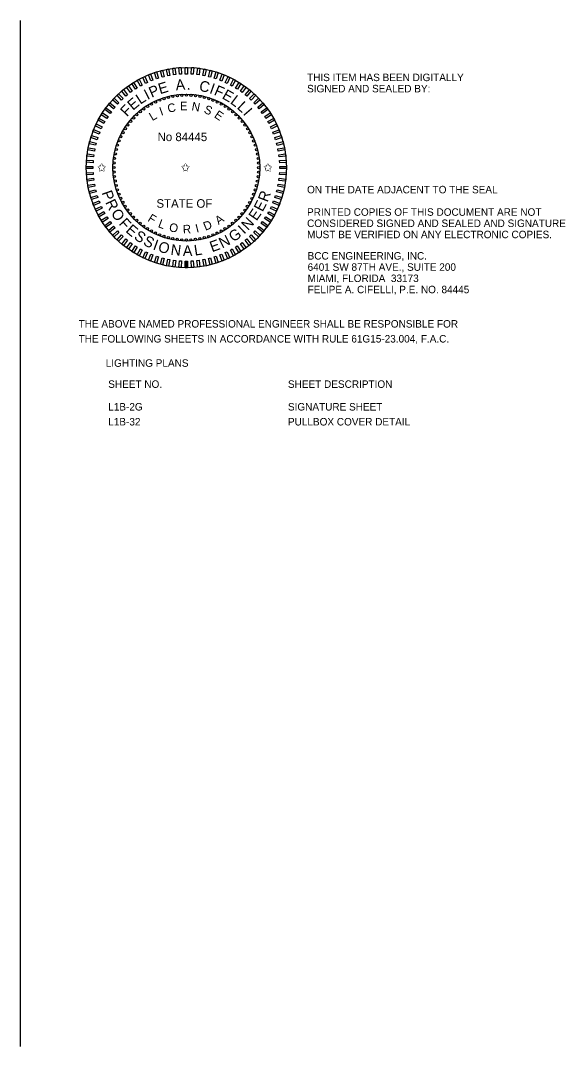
# Model space of a CAD drawing. Extents: x -811.2 to -755.6, y -2295.2 to -2235.1.
# Drawn here: x -760.66 to -755.56, y -2282.15 to -2272.55 of the extents above; entities that cross this region are included whole.
import ezdxf

# ---------------------------------------------------------------- set-up
doc = ezdxf.new("R2010")
doc.units = 0
for name, color, linetype in [('Logo_dp', 7, 'Continuous'), ('NonPlottingEle_dp', 7, 'Continuous'), ('SheetBorder_dp', 7, 'Continuous'), ('TextMisc', 7, 'Continuous'), ('TextNotes', 7, 'Continuous')]:
    doc.layers.add(name, color=color, linetype=linetype)

msp = doc.modelspace()

# ---------------------------------------------------------------- linework, layer by layer
at = {"layer": 'Logo_dp'}
for p, q in [((-759.1177, -2274.859), (-759.1179, -2274.7965)), ((-759.1077, -2274.859), (-759.1079, -2274.7965)), ((-759.0977, -2274.859), (-759.0979, -2274.7965))]:
    msp.add_line(p, q, dxfattribs=at)
for points in [[(-759.2073, -2273.0521), (-759.2273, -2273.0546), (-759.2351, -2272.9927), (-759.2151, -2272.9902)], [(-759.1525, -2273.0476), (-759.1726, -2273.0488), (-759.1765, -2272.9865), (-759.1564, -2272.9852)], [(-759.0975, -2273.0465), (-759.1177, -2273.0465), (-759.1177, -2272.984), (-759.0975, -2272.984)], [(-759.0426, -2273.0488), (-759.0627, -2273.0476), (-759.0588, -2272.9853), (-759.0387, -2272.9865)], [(-758.9879, -2273.0547), (-759.0079, -2273.0521), (-759.0001, -2272.9902), (-758.9801, -2272.9927)], [(-759.471, -2273.1254), (-759.4893, -2273.134), (-759.5159, -2273.0775), (-759.4976, -2273.0689)], [(-759.4203, -2273.1042), (-759.4391, -2273.1116), (-759.4621, -2273.0536), (-759.4433, -2273.0461)], [(-759.3684, -2273.0862), (-759.3876, -2273.0924), (-759.4069, -2273.033), (-759.3877, -2273.0268)], [(-759.3154, -2273.0714), (-759.335, -2273.0765), (-759.3505, -2273.016), (-759.331, -2273.011)], [(-759.2617, -2273.0601), (-759.2815, -2273.0638), (-759.2932, -2273.0025), (-759.2734, -2272.9987)], [(-758.9337, -2273.0639), (-758.9536, -2273.0601), (-758.9419, -2272.9988), (-758.922, -2273.0026)], [(-758.8802, -2273.0765), (-758.8998, -2273.0715), (-758.8842, -2273.011), (-758.8647, -2273.016)], [(-758.8276, -2273.0925), (-758.8468, -2273.0862), (-758.8275, -2273.0268), (-758.8083, -2273.0331)], [(-758.7761, -2273.1117), (-758.7949, -2273.1042), (-758.7719, -2273.0462), (-758.7531, -2273.0536)], [(-758.7259, -2273.1341), (-758.7442, -2273.1255), (-758.7176, -2273.069), (-758.6993, -2273.0776)], [(-759.6138, -2273.2076), (-759.6301, -2273.2195), (-759.6668, -2273.169), (-759.6505, -2273.1571)], [(-759.568, -2273.1772), (-759.585, -2273.1881), (-759.6185, -2273.1353), (-759.6014, -2273.1245)], [(-759.5203, -2273.1498), (-759.538, -2273.1595), (-759.5681, -2273.1048), (-759.5504, -2273.0951)], [(-758.6772, -2273.1596), (-758.6949, -2273.1499), (-758.6648, -2273.0952), (-758.6471, -2273.1049)], [(-758.6302, -2273.1882), (-758.6473, -2273.1773), (-758.6138, -2273.1246), (-758.5968, -2273.1354)], [(-758.5851, -2273.2196), (-758.6015, -2273.2077), (-758.5648, -2273.1572), (-758.5484, -2273.1691)], [(-759.7386, -2273.3151), (-759.7524, -2273.3298), (-759.7979, -2273.2871), (-759.7841, -2273.2723)], [(-759.6993, -2273.2767), (-759.714, -2273.2905), (-759.7567, -2273.245), (-759.742, -2273.2311)], [(-759.6576, -2273.2408), (-759.6732, -2273.2537), (-759.713, -2273.2055), (-759.6974, -2273.1927)], [(-758.5421, -2273.2538), (-758.5576, -2273.2409), (-758.5178, -2273.1928), (-758.5023, -2273.2057)], [(-758.5013, -2273.2906), (-758.516, -2273.2768), (-758.4732, -2273.2313), (-758.4585, -2273.2451)], [(-758.4628, -2273.3299), (-758.4767, -2273.3152), (-758.4312, -2273.2725), (-758.4173, -2273.2872)], [(-759.8096, -2273.3989), (-759.8215, -2273.4153), (-759.872, -2273.3786), (-759.8601, -2273.3622)], [(-759.7754, -2273.3559), (-759.7883, -2273.3714), (-759.8364, -2273.3316), (-759.8235, -2273.3161)], [(-758.427, -2273.3716), (-758.4398, -2273.356), (-758.3917, -2273.3162), (-758.3789, -2273.3318)], [(-758.3938, -2273.4154), (-758.4057, -2273.3991), (-758.3551, -2273.3624), (-758.3433, -2273.3787)], [(-759.8696, -2273.491), (-759.8793, -2273.5087), (-759.934, -2273.4786), (-759.9243, -2273.461)], [(-759.841, -2273.444), (-759.8519, -2273.4611), (-759.9046, -2273.4276), (-759.8938, -2273.4106)], [(-758.3634, -2273.4612), (-758.3742, -2273.4442), (-758.3215, -2273.4107), (-758.3107, -2273.4278)], [(-758.336, -2273.5089), (-758.3457, -2273.4912), (-758.291, -2273.4611), (-758.2813, -2273.4788)], [(-759.9175, -2273.5899), (-759.925, -2273.6087), (-759.983, -2273.5857), (-759.9756, -2273.5669)], [(-759.8951, -2273.5397), (-759.9037, -2273.558), (-759.9602, -2273.5314), (-759.9516, -2273.5131)], [(-758.3116, -2273.5582), (-758.3202, -2273.5399), (-758.2637, -2273.5133), (-758.2551, -2273.5316)], [(-758.2904, -2273.6089), (-758.2978, -2273.5901), (-758.2397, -2273.5671), (-758.2323, -2273.5859)], [(-759.9367, -2273.6414), (-759.943, -2273.6606), (-760.0024, -2273.6413), (-759.9961, -2273.6221)], [(-758.2723, -2273.6608), (-758.2786, -2273.6416), (-758.2192, -2273.6223), (-758.213, -2273.6415)], [(-759.9653, -2273.7475), (-759.9691, -2273.7674), (-760.0304, -2273.7557), (-760.0266, -2273.7358)], [(-759.9527, -2273.694), (-759.9577, -2273.7136), (-760.0182, -2273.6981), (-760.0132, -2273.6785)], [(-758.2576, -2273.7138), (-758.2626, -2273.6942), (-758.2022, -2273.6787), (-758.1971, -2273.6982)], [(-758.2463, -2273.7675), (-758.25, -2273.7477), (-758.1887, -2273.736), (-758.1849, -2273.7558)], [(-759.9804, -2273.8564), (-759.9816, -2273.8765), (-760.0439, -2273.8726), (-760.0427, -2273.8525)], [(-759.9745, -2273.8017), (-759.9771, -2273.8218), (-760.039, -2273.8139), (-760.0365, -2273.7939)], [(-758.2383, -2273.8219), (-758.2408, -2273.8019), (-758.1789, -2273.7941), (-758.1763, -2273.8141)], [(-758.2337, -2273.8767), (-758.235, -2273.8566), (-758.1727, -2273.8527), (-758.1714, -2273.8728)], [(-759.9827, -2273.9113), (-759.9827, -2273.9315), (-760.0452, -2273.9315), (-760.0452, -2273.9113)], [(-758.2327, -2273.9317), (-758.2327, -2273.9115), (-758.1702, -2273.9115), (-758.1702, -2273.9317)], [(-759.9816, -2273.9663), (-759.9804, -2273.9864), (-760.0427, -2273.9904), (-760.044, -2273.9702)], [(-759.9771, -2274.0211), (-759.9746, -2274.0411), (-760.0365, -2274.0489), (-760.039, -2274.0289)], [(-758.2408, -2274.0413), (-758.2383, -2274.0213), (-758.1764, -2274.0291), (-758.1789, -2274.0491)], [(-758.235, -2273.9866), (-758.2338, -2273.9665), (-758.1714, -2273.9704), (-758.1727, -2273.9905)], [(-759.9691, -2274.0755), (-759.9653, -2274.0953), (-760.0267, -2274.107), (-760.0305, -2274.0872)], [(-759.9578, -2274.1293), (-759.9527, -2274.1488), (-760.0132, -2274.1643), (-760.0182, -2274.1448)], [(-758.2627, -2274.149), (-758.2577, -2274.1294), (-758.1972, -2274.145), (-758.2022, -2274.1645)], [(-758.2501, -2274.0955), (-758.2463, -2274.0756), (-758.185, -2274.0873), (-758.1887, -2274.1072)], [(-759.943, -2274.1822), (-759.9368, -2274.2014), (-759.9962, -2274.2207), (-760.0024, -2274.2015)], [(-759.925, -2274.2342), (-759.9176, -2274.2529), (-759.9756, -2274.2759), (-759.9831, -2274.2571)], [(-758.2979, -2274.2531), (-758.2904, -2274.2343), (-758.2324, -2274.2573), (-758.2398, -2274.2761)], [(-758.2786, -2274.2016), (-758.2724, -2274.1824), (-758.213, -2274.2017), (-758.2193, -2274.2209)], [(-759.9038, -2274.2849), (-759.8952, -2274.3031), (-759.9517, -2274.3297), (-759.9603, -2274.3114)], [(-759.8794, -2274.3341), (-759.8697, -2274.3518), (-759.9244, -2274.3819), (-759.9341, -2274.3642)], [(-758.3458, -2274.352), (-758.3361, -2274.3343), (-758.2814, -2274.3644), (-758.2911, -2274.3821)], [(-758.3203, -2274.3033), (-758.3117, -2274.285), (-758.2552, -2274.3116), (-758.2638, -2274.3299)], [(-759.852, -2274.3818), (-759.8411, -2274.3988), (-759.8939, -2274.4323), (-759.9047, -2274.4152)], [(-759.8216, -2274.4276), (-759.8097, -2274.4439), (-759.8602, -2274.4806), (-759.8721, -2274.4643)], [(-758.4058, -2274.4441), (-758.3939, -2274.4277), (-758.3434, -2274.4644), (-758.3553, -2274.4808)], [(-758.3743, -2274.399), (-758.3635, -2274.3819), (-758.3108, -2274.4154), (-758.3216, -2274.4324)], [(-759.7884, -2274.4714), (-759.7755, -2274.487), (-759.8237, -2274.5268), (-759.8365, -2274.5112)], [(-759.7525, -2274.5131), (-759.7387, -2274.5278), (-759.7842, -2274.5705), (-759.7981, -2274.5558)], [(-758.4768, -2274.5279), (-758.463, -2274.5132), (-758.4175, -2274.556), (-758.4313, -2274.5707)], [(-758.44, -2274.4871), (-758.4271, -2274.4716), (-758.379, -2274.5114), (-758.3919, -2274.5269)], [(-759.7141, -2274.5524), (-759.6994, -2274.5662), (-759.7421, -2274.6117), (-759.7569, -2274.5979)], [(-759.6733, -2274.5892), (-759.6578, -2274.6021), (-759.6976, -2274.6502), (-759.7131, -2274.6373)], [(-759.6303, -2274.6234), (-759.6139, -2274.6353), (-759.6506, -2274.6858), (-759.667, -2274.6739)], [(-758.6016, -2274.6354), (-758.5853, -2274.6235), (-758.5486, -2274.6741), (-758.5649, -2274.6859)], [(-758.5578, -2274.6022), (-758.5422, -2274.5894), (-758.5024, -2274.6375), (-758.518, -2274.6503)], [(-758.5161, -2274.5663), (-758.5014, -2274.5525), (-758.4587, -2274.598), (-758.4734, -2274.6119)], [(-759.5852, -2274.6549), (-759.5681, -2274.6657), (-759.6016, -2274.7184), (-759.6186, -2274.7076)], [(-759.5382, -2274.6834), (-759.5205, -2274.6931), (-759.5506, -2274.7478), (-759.5682, -2274.7381)], [(-759.4895, -2274.7089), (-759.4712, -2274.7175), (-759.4978, -2274.774), (-759.5161, -2274.7654)], [(-758.7443, -2274.7176), (-758.7261, -2274.709), (-758.6995, -2274.7655), (-758.7178, -2274.7741)], [(-758.6951, -2274.6932), (-758.6774, -2274.6835), (-758.6473, -2274.7382), (-758.665, -2274.7479)], [(-758.6474, -2274.6658), (-758.6304, -2274.655), (-758.5969, -2274.7077), (-758.614, -2274.7185)], [(-759.4393, -2274.7313), (-759.4205, -2274.7388), (-759.4435, -2274.7968), (-759.4623, -2274.7894)], [(-759.3878, -2274.7506), (-759.3686, -2274.7568), (-759.3879, -2274.8162), (-759.4071, -2274.8099)], [(-759.3352, -2274.7665), (-759.3156, -2274.7715), (-759.3311, -2274.832), (-759.3507, -2274.827)], [(-759.2817, -2274.7791), (-759.2618, -2274.7829), (-759.2735, -2274.8442), (-759.2934, -2274.8405)], [(-759.2275, -2274.7884), (-759.2074, -2274.7909), (-759.2153, -2274.8528), (-759.2353, -2274.8503)], [(-759.1728, -2274.7942), (-759.1527, -2274.7954), (-759.1566, -2274.8578), (-759.1767, -2274.8565)], [(-759.1179, -2274.7965), (-759.0977, -2274.7965), (-759.0977, -2274.859), (-759.1179, -2274.859)], [(-759.0629, -2274.7954), (-759.0428, -2274.7942), (-759.0388, -2274.8565), (-759.059, -2274.8578)], [(-759.0081, -2274.7909), (-758.9881, -2274.7884), (-758.9803, -2274.8503), (-759.0003, -2274.8529)], [(-758.9537, -2274.7829), (-758.9339, -2274.7792), (-758.9222, -2274.8405), (-758.942, -2274.8443)], [(-758.8999, -2274.7716), (-758.8804, -2274.7666), (-758.8649, -2274.827), (-758.8844, -2274.8321)], [(-758.847, -2274.7569), (-758.8278, -2274.7506), (-758.8085, -2274.81), (-758.8277, -2274.8162)], [(-758.795, -2274.7388), (-758.7763, -2274.7314), (-758.7533, -2274.7895), (-758.7721, -2274.7969)]]:
    msp.add_lwpolyline(points, close=True, dxfattribs=at)
for centre in [(-759.3165, -2273.277), (-759.2756, -2273.2652), (-759.2341, -2273.2559), (-759.192, -2273.2493), (-759.1497, -2273.2453), (-759.1071, -2273.244), (-759.0646, -2273.2454), (-759.0222, -2273.2495), (-758.9802, -2273.2561), (-758.9387, -2273.2655), (-758.8978, -2273.2774), (-759.5054, -2273.3731), (-759.4702, -2273.3492), (-759.4336, -2273.3276), (-759.3956, -2273.3083), (-759.3566, -2273.2914), (-758.8578, -2273.2918), (-758.8187, -2273.3088), (-758.7808, -2273.3281), (-758.7442, -2273.3498), (-758.709, -2273.3738), (-759.6012, -2273.4573), (-759.571, -2273.4273), (-759.5391, -2273.3991), (-758.6754, -2273.3999), (-758.6435, -2273.428), (-758.6135, -2273.4582), (-759.6794, -2273.558), (-759.6554, -2273.5228), (-759.6293, -2273.4892), (-758.5853, -2273.4901), (-758.5593, -2273.5238), (-758.5354, -2273.559), (-759.7374, -2273.6716), (-759.7204, -2273.6325), (-759.7011, -2273.5946), (-758.5138, -2273.5956), (-758.4945, -2273.6336), (-758.4776, -2273.6726), (-759.7637, -2273.7525), (-759.7518, -2273.7116), (-758.4632, -2273.7127), (-758.4514, -2273.7536), (-759.7797, -2273.836), (-759.7731, -2273.794), (-758.4421, -2273.7951), (-758.4355, -2273.8372), (-759.7852, -2273.9209), (-759.7838, -2273.8784), (-758.4315, -2273.8795), (-758.4302, -2273.9221), (-759.7839, -2273.9635), (-759.7799, -2274.0059), (-759.7733, -2274.0479), (-758.4423, -2274.049), (-758.4356, -2274.007), (-758.4316, -2273.9646), (-759.764, -2274.0894), (-759.7522, -2274.1303), (-758.4636, -2274.1314), (-758.4516, -2274.0905), (-759.7378, -2274.1704), (-759.7209, -2274.2094), (-759.7016, -2274.2474), (-758.5143, -2274.2484), (-758.4949, -2274.2105), (-758.478, -2274.1714), (-759.68, -2274.284), (-759.6561, -2274.3193), (-758.5599, -2274.3202), (-758.536, -2274.285), (-759.63, -2274.3529), (-759.6019, -2274.3849), (-759.5719, -2274.415), (-758.6443, -2274.4157), (-758.6142, -2274.3857), (-758.5861, -2274.3538), (-759.54, -2274.4431), (-759.5064, -2274.4693), (-759.4712, -2274.4932), (-759.4346, -2274.5149), (-759.3967, -2274.5343), (-758.8198, -2274.5347), (-758.7818, -2274.5154), (-758.7452, -2274.4938), (-758.7099, -2274.4699), (-758.6763, -2274.4439), (-759.3576, -2274.5512), (-759.3176, -2274.5656), (-759.2767, -2274.5776), (-759.2352, -2274.5869), (-759.1932, -2274.5936), (-759.1508, -2274.5976), (-759.1077, -2274.599), (-759.0657, -2274.5977), (-759.0233, -2274.5937), (-758.9813, -2274.5871), (-758.9398, -2274.5778), (-758.8989, -2274.566), (-758.8588, -2274.5516)]:
    msp.add_circle(centre, 0.01, dxfattribs=at)
at = {"layer": 'NonPlottingEle_dp'}
for radius in [0.9375, 0.6875]:
    msp.add_circle((-759.1077, -2273.9215), radius, dxfattribs=at)
at = {"layer": 'SheetBorder_dp'}
msp.add_line((-760.6605, -2282.1457), (-760.6605, -2272.5457), dxfattribs=at)

# ---------------------------------------------------------------- texts
at = {"layer": 'Logo_dp'}
for s, height, rotation, p in [('P', 0.1, 23.28287, (-759.4329, -2273.2694)), ('E', 0.1, 16.54261, (-759.3541, -2273.2358)), ('A', 0.1, 4.42103, (-759.2046, -2273.1993)), ('.', 0.1, 356.65403, (-759.1061, -2273.1929)), ('C', 0.1, 347.7999, (-758.994, -2273.2018)), ('I', 0.1, 340.0631, (-758.8981, -2273.2236)), ('F', 0.1, 336.52991, (-758.8555, -2273.2379)), ('E', 0.1, 40.12142, (-759.6078, -2273.3916)), ('L', 0.1, 33.07918, (-759.5391, -2273.3343)), ('I', 0.1, 26.81606, (-759.4724, -2273.2907)), ('E', 0.1, 330.07956, (-758.7803, -2273.2705)), ('L', 0.1, 323.03732, (-758.703, -2273.3156)), ('F', 0.1, 46.57177, (-759.6642, -2273.4511)), ('I', 0.08, 20.01168, (-759.3434, -2273.4374)), ('C', 0.08, 12.20255, (-759.2754, -2273.4099)), ('E', 0.08, 0.41861, (-759.1674, -2273.3864)), ('N', 0.08, 349.29143, (-759.063, -2273.385)), ('S', 0.08, 337.02207, (-758.95, -2273.4067)), ('L', 0.1, 316.7742, (-758.6393, -2273.3634)), ('I', 0.1, 310.51108, (-758.5812, -2273.4178)), ('L', 0.08, 30.40215, (-759.4268, -2273.4879)), ('E', 0.08, 325.86633, (-758.8534, -2273.4469)), ('P', 0.1, 289.40551, (-759.9024, -2274.1561)), ('R', 0.1, 69.5134, (-758.3475, -2274.2512)), ('R', 0.1, 296.14576, (-759.8694, -2274.2477)), ('E', 0.1, 62.47116, (-758.3937, -2274.3419)), ('O', 0.1, 303.96711, (-759.8179, -2274.3484)), ('E', 0.1, 55.42892, (-758.4506, -2274.4263)), ('F', 0.1, 312.62798, (-759.7455, -2274.4504)), ('F', 0.08, 328.72408, (-759.4757, -2274.4181)), ('L', 0.08, 339.29159, (-759.3784, -2274.4772)), ('D', 0.08, 22.01279, (-758.9296, -2274.5134)), ('A', 0.08, 34.49917, (-758.8059, -2274.4609)), ('N', 0.1, 47.17876, (-758.5298, -2274.5154)), ('E', 0.1, 319.07833, (-759.6821, -2274.5187)), ('S', 0.1, 326.12056, (-759.6045, -2274.5847)), ('O', 0.08, 349.68206, (-759.2738, -2274.5169)), ('R', 0.08, 2.33977, (-759.1393, -2274.5388)), ('I', 0.08, 14.20366, (-759.0117, -2274.5321)), ('G', 0.1, 35.11153, (-758.6667, -2274.623)), ('I', 0.1, 43.64556, (-758.5675, -2274.5498)), ('S', 0.1, 333.193, (-759.5191, -2274.6408)), ('I', 0.1, 340.26543, (-759.4274, -2274.686)), ('O', 0.1, 343.79863, (-759.3797, -2274.7042)), ('E', 0.1, 19.81912, (-758.8674, -2274.7145)), ('N', 0.1, 26.86136, (-758.772, -2274.6791)), ('N', 0.1, 352.45949, (-759.2587, -2274.7362)), ('A', 0.1, 0.70966, (-759.1402, -2274.7495)), ('L', 0.1, 8.47665, (-759.028, -2274.7463))]:
    msp.add_text(s, height=height, rotation=rotation, dxfattribs=at).set_placement(p)
for s, p in [('No 84445', (-759.3767, -2273.6743)), ('✩', (-759.9427, -2273.9595)), ('✩', (-759.158, -2273.9595)), ('✩', (-758.3861, -2273.9595)), ('STATE OF', (-759.3874, -2274.2977))]:
    msp.add_text(s, height=0.08, dxfattribs=at).set_placement(p)
at = {"layer": 'TextMisc'}
for s, p in [('THIS ITEM HAS BEEN DIGITALLY', (-757.9772, -2273.1128)), ('SIGNED AND SEALED BY:', (-757.9772, -2273.2178)), ('ON THE DATE ADJACENT TO THE SEAL', (-757.9772, -2274.1628)), ('PRINTED COPIES OF THIS DOCUMENT ARE NOT ', (-757.9772, -2274.3728)), ('CONSIDERED SIGNED AND SEALED AND SIGNATURE ', (-757.9772, -2274.4778)), ('MUST BE VERIFIED ON ANY ELECTRONIC COPIES.', (-757.9772, -2274.5828)), ('BCC ENGINEERING, INC.', (-757.9722, -2274.7827)), ('6401 SW 87TH AVE., SUITE 200', (-757.9722, -2274.8877)), ('MIAMI, FLORIDA  33173', (-757.9722, -2274.9927)), ('FELIPE A. CIFELLI, P.E. NO. 84445', (-757.9722, -2275.0977)), ('THE ABOVE NAMED PROFESSIONAL ENGINEER SHALL BE RESPONSIBLE FOR ', (-760.1163, -2275.4188)), ('THE FOLLOWING SHEETS IN ACCORDANCE WITH RULE 61G15-23.004, F.A.C.', (-760.1163, -2275.5588)), ('LIGHTING PLANS', (-759.8625, -2275.7858))]:
    msp.add_text(s, height=0.07, dxfattribs=at).set_placement(p)
at = {"layer": 'TextNotes'}
for s, p in [('SHEET NO.', (-759.8391, -2275.9828)), ('SHEET DESCRIPTION', (-758.1562, -2275.9828)), ('L1B-2G', (-759.8391, -2276.195)), ('SIGNATURE SHEET', (-758.1562, -2276.195)), ('L1B-32', (-759.8391, -2276.335)), ('PULLBOX COVER DETAIL', (-758.1562, -2276.335))]:
    msp.add_text(s, height=0.07, dxfattribs=at).set_placement(p)

doc.saveas('drawing.dxf')
